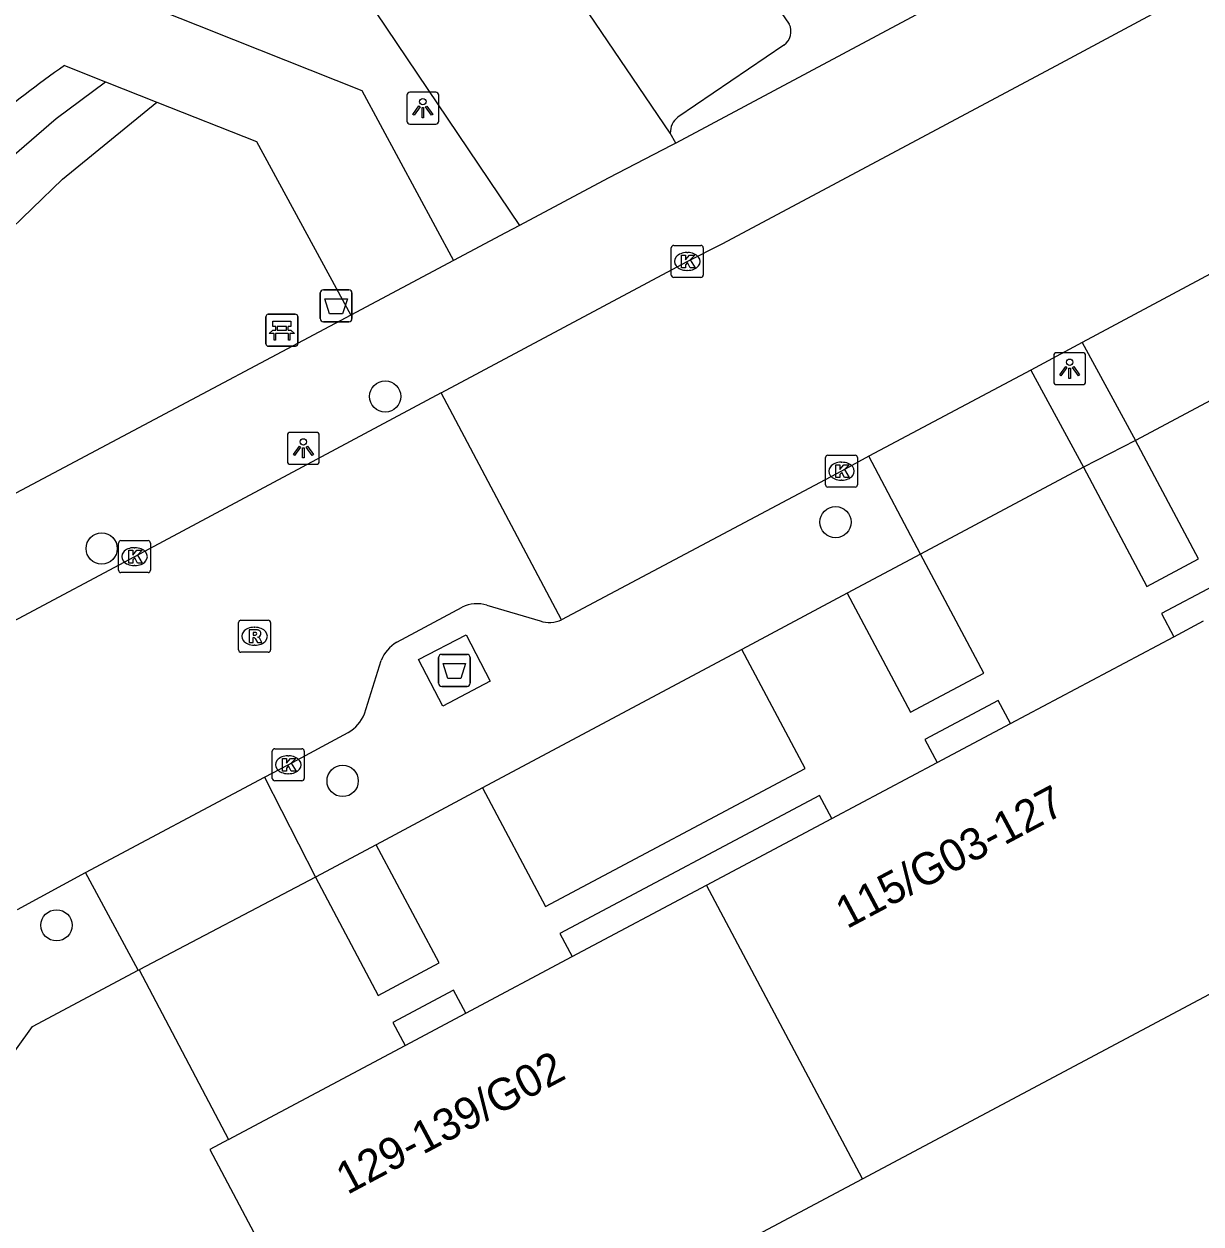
# Model space of a CAD drawing. Extents: x 159675 to 160530, y 382179 to 382901.
# Drawn here: x 159893.75 to 159930.56, y 382360.88 to 382398.41 of the extents above; entities that cross this region are included whole.
import ezdxf

# ---------------------------------------------------------------- set-up
doc = ezdxf.new("R2010")
doc.units = 0
for name, color, linetype in [('IMGEO_Afval_apart_plaats', 7, 'Continuous'), ('IMGEO_Afvalbak', 7, 'Continuous'), ('IMGEO_Bank', 7, 'Continuous'), ('IMGEO_Boom', 7, 'Continuous'), ('IMGEO_Groenvoorziening', 7, 'Continuous'), ('IMGEO_Kolk', 7, 'Continuous'), ('IMGEO_Lichtpunt', 7, 'Continuous'), ('IMGEO_Pand', 7, 'Continuous'), ('IMGEO_Pand_nummerreeks', 7, 'Continuous'), ('IMGEO_Parkeervlak_open', 7, 'Continuous'), ('IMGEO_Rijbaan_lokaal_gesloten', 7, 'Continuous'), ('IMGEO_Rijbaan_lokaal_open', 7, 'Continuous'), ('IMGEO_Rioolput', 7, 'Continuous'), ('IMGEO_Voetpad_gesloten', 7, 'Continuous'), ('IMGEO_Voetpad_open', 7, 'Continuous')]:
    doc.layers.add(name, color=color, linetype=linetype)

msp = doc.modelspace()

# ---------------------------------------------------------------- linework, layer by layer
at = {"layer": 'IMGEO_Afval_apart_plaats'}
for p, q in [((159906.817, 382378.693), (159907.607, 382378.693)), ((159907.607, 382378.693), (159906.817, 382378.693)), ((159906.717, 382377.793), (159906.717, 382378.593)), ((159906.717, 382378.593), (159906.717, 382377.793)), ((159907.707, 382378.593), (159907.707, 382377.793)), ((159907.707, 382377.793), (159907.707, 382378.593)), ((159907.607, 382377.693), (159906.817, 382377.693)), ((159906.817, 382377.693), (159907.607, 382377.693))]:
    msp.add_line(p, q, dxfattribs=at)
msp.add_lwpolyline([(159906.86, 382378.407), (159907.564, 382378.407), (159907.415, 382377.937), (159907.009, 382377.937), (159906.86, 382378.407)], dxfattribs=at)
for centre, start, end in [((159906.817, 382378.593), 90, 180), ((159906.817, 382378.593), 90, 180), ((159907.607, 382378.593), 0, 90), ((159907.607, 382378.593), 360, 90), ((159906.817, 382377.793), 180, 270), ((159906.817, 382377.793), 180, 270), ((159907.607, 382377.793), 270, 0), ((159907.607, 382377.793), 270, 0)]:
    msp.add_arc(centre, 0.1, start, end, dxfattribs=at)
at = {"layer": 'IMGEO_Afvalbak'}
for p, q in [((159903.019, 382389.197), (159903.019, 382389.997)), ((159903.019, 382389.997), (159903.019, 382389.197)), ((159903.119, 382390.097), (159903.909, 382390.097)), ((159903.909, 382390.097), (159903.119, 382390.097)), ((159904.009, 382389.997), (159904.009, 382389.197)), ((159904.009, 382389.197), (159904.009, 382389.997)), ((159903.909, 382389.097), (159903.119, 382389.097)), ((159903.119, 382389.097), (159903.909, 382389.097))]:
    msp.add_line(p, q, dxfattribs=at)
msp.add_lwpolyline([(159903.162, 382389.811), (159903.866, 382389.811), (159903.717, 382389.341), (159903.311, 382389.341), (159903.162, 382389.811)], dxfattribs=at)
for centre, start, end in [((159903.119, 382389.997), 90, 180), ((159903.119, 382389.997), 90, 180), ((159903.909, 382389.997), 0, 90), ((159903.909, 382389.997), 360, 90), ((159903.119, 382389.197), 180, 270), ((159903.119, 382389.197), 180, 270), ((159903.909, 382389.197), 270, 0), ((159903.909, 382389.197), 270, 0)]:
    msp.add_arc(centre, 0.1, start, end, dxfattribs=at)
at = {"layer": 'IMGEO_Bank'}
for p, q in [((159901.318, 382388.408), (159901.318, 382389.249)), ((159901.318, 382389.249), (159901.318, 382388.408)), ((159901.393, 382389.333), (159902.234, 382389.333)), ((159902.234, 382389.333), (159901.393, 382389.333)), ((159902.318, 382389.258), (159902.318, 382388.417)), ((159902.318, 382388.417), (159902.318, 382389.258)), ((159901.627, 382388.839), (159901.627, 382388.945)), ((159901.671, 382388.945), (159901.671, 382388.839)), ((159901.959, 382388.951), (159901.677, 382388.951)), ((159901.677, 382388.833), (159901.959, 382388.833)), ((159901.965, 382388.839), (159901.965, 382388.945)), ((159902.009, 382388.945), (159902.009, 382388.839)), ((159902.015, 382388.731), (159901.622, 382388.731)), ((159902.243, 382388.333), (159901.402, 382388.333)), ((159901.402, 382388.333), (159902.243, 382388.333))]:
    msp.add_line(p, q, dxfattribs=at)
for points in [[(159901.565, 382388.731), (159901.423, 382388.731), (159901.535, 382388.833), (159901.621, 382388.833)], [(159901.621, 382388.951), (159901.535, 382388.951), (159901.535, 382389.112), (159902.098, 382389.112), (159902.098, 382388.951), (159902.015, 382388.951)], [(159902.015, 382388.833), (159902.098, 382388.833), (159902.21, 382388.731), (159902.071, 382388.731)], [(159901.615, 382388.724), (159901.615, 382388.517), (159901.572, 382388.517), (159901.572, 382388.724)], [(159902.065, 382388.724), (159902.065, 382388.517), (159902.021, 382388.517), (159902.021, 382388.724)]]:
    msp.add_lwpolyline(points, dxfattribs=at)
for centre, radius, start, end in [((159901.396, 382389.255), 0.0779, 92.4484, 184.2845), ((159901.396, 382389.255), 0.0779, 92.4484, 184.2845), ((159902.24, 382389.255), 0.0779, 2.4484, 94.2845), ((159902.24, 382389.255), 0.0779, 2.4484, 94.2845), ((159901.62, 382388.944), 0.00671, 2.8957, 87.1043), ((159901.62, 382388.84), 0.00671, 272.8957, 357.1043), ((159901.677, 382388.944), 0.00671, 92.8957, 177.1043), ((159901.677, 382388.84), 0.00671, 182.8957, 267.1043), ((159901.959, 382388.944), 0.00671, 2.8957, 87.1043), ((159901.959, 382388.84), 0.00671, 272.8957, 357.1043), ((159902.016, 382388.944), 0.00671, 92.8957, 177.1043), ((159902.016, 382388.84), 0.00671, 182.8957, 267.1043), ((159901.565, 382388.724), 0.00671, 2.8957, 87.1043), ((159901.622, 382388.724), 0.00671, 92.8957, 177.1043), ((159902.014, 382388.724), 0.00671, 2.8957, 87.1043), ((159902.071, 382388.724), 0.00671, 92.8957, 177.1043), ((159901.396, 382388.411), 0.0779, 182.4484, 274.2845), ((159901.396, 382388.411), 0.0779, 182.4484, 274.2845), ((159902.24, 382388.411), 0.0779, 272.4484, 4.2845), ((159902.24, 382388.411), 0.0779, 272.4484, 4.2845)]:
    msp.add_arc(centre, radius, start, end, dxfattribs=at)
at = {"layer": 'IMGEO_Boom'}
for centre in [(159905.05, 382386.76), (159919.13, 382382.831), (159896.182, 382382.003), (159903.718, 382374.735), (159894.772, 382370.219)]:
    msp.add_circle(centre, 0.489, dxfattribs=at)
at = {"layer": 'IMGEO_Groenvoorziening'}
for points in [[(159880.868, 382381.168), (159884.215, 382385.459), (159885.111, 382386.512), (159888.277, 382389.857), (159894.758, 382395.456), (159896.302, 382396.602)], [(159882.23, 382378.883), (159884.721, 382382.187), (159885.15, 382382.548), (159889.821, 382388.351), (159891.149, 382389.882), (159894.953, 382393.558), (159897.904, 382395.97)]]:
    msp.add_lwpolyline(points, dxfattribs=at)
at = {"layer": 'IMGEO_Kolk'}
for p, q in [((159914.069, 382391.483), (159914.921, 382391.483)), ((159913.994, 382390.557), (159913.994, 382391.409)), ((159914.482, 382391.263), (159914.507, 382391.263)), ((159914.995, 382391.409), (159914.995, 382390.557)), ((159914.505, 382390.703), (159914.48, 382390.703)), ((159914.921, 382390.483), (159914.069, 382390.483)), ((159918.816, 382383.997), (159918.816, 382384.849)), ((159918.891, 382384.923), (159919.743, 382384.923)), ((159919.304, 382384.703), (159919.329, 382384.703)), ((159919.817, 382384.849), (159919.817, 382383.997)), ((159919.327, 382384.143), (159919.302, 382384.143)), ((159919.743, 382383.923), (159918.891, 382383.923)), ((159896.709, 382381.325), (159896.709, 382382.177)), ((159896.784, 382382.251), (159897.636, 382382.251)), ((159897.71, 382382.177), (159897.71, 382381.325)), ((159897.197, 382382.031), (159897.222, 382382.031)), ((159897.22, 382381.471), (159897.195, 382381.471)), ((159897.636, 382381.251), (159896.784, 382381.251)), ((159901.593, 382375.741), (159902.445, 382375.741)), ((159901.518, 382374.815), (159901.518, 382375.667)), ((159902.006, 382375.521), (159902.031, 382375.521)), ((159902.519, 382375.667), (159902.519, 382374.815)), ((159902.029, 382374.961), (159902.004, 382374.961)), ((159902.445, 382374.741), (159901.593, 382374.741))]:
    msp.add_line(p, q, dxfattribs=at)
for points in [[(159914.069, 382391.483), (159914.921, 382391.483)], [(159913.994, 382390.557), (159913.994, 382391.409)], [(159914.315, 382391.183), (159914.438, 382391.183), (159914.438, 382391.032), (159914.568, 382391.183), (159914.732, 382391.183), (159914.586, 382391.032), (159914.739, 382390.783), (159914.587, 382390.783), (159914.502, 382390.947), (159914.438, 382390.88), (159914.438, 382390.783), (159914.315, 382390.783), (159914.315, 382391.183)], [(159914.995, 382391.409), (159914.995, 382390.557)], [(159914.921, 382390.483), (159914.069, 382390.483)], [(159918.816, 382383.997), (159918.816, 382384.849)], [(159918.891, 382384.923), (159919.743, 382384.923)], [(159919.817, 382384.849), (159919.817, 382383.997)], [(159919.137, 382384.623), (159919.26, 382384.623), (159919.26, 382384.472), (159919.39, 382384.623), (159919.554, 382384.623), (159919.408, 382384.472), (159919.561, 382384.223), (159919.409, 382384.223), (159919.324, 382384.387), (159919.26, 382384.32), (159919.26, 382384.223), (159919.137, 382384.223), (159919.137, 382384.623)], [(159919.743, 382383.923), (159918.891, 382383.923)], [(159896.709, 382381.325), (159896.709, 382382.177)], [(159896.784, 382382.251), (159897.636, 382382.251)], [(159897.71, 382382.177), (159897.71, 382381.325)], [(159897.03, 382381.951), (159897.153, 382381.951), (159897.153, 382381.8), (159897.283, 382381.951), (159897.447, 382381.951), (159897.301, 382381.8), (159897.454, 382381.551), (159897.302, 382381.551), (159897.217, 382381.715), (159897.153, 382381.648), (159897.153, 382381.551), (159897.03, 382381.551), (159897.03, 382381.951)], [(159897.636, 382381.251), (159896.784, 382381.251)], [(159901.593, 382375.741), (159902.445, 382375.741)], [(159901.518, 382374.815), (159901.518, 382375.667)], [(159901.839, 382375.441), (159901.962, 382375.441), (159901.962, 382375.29), (159902.092, 382375.441), (159902.256, 382375.441), (159902.11, 382375.29), (159902.263, 382375.041), (159902.111, 382375.041), (159902.026, 382375.205), (159901.962, 382375.138), (159901.962, 382375.041), (159901.839, 382375.041), (159901.839, 382375.441)], [(159902.519, 382375.667), (159902.519, 382374.815)], [(159902.445, 382374.741), (159901.593, 382374.741)]]:
    msp.add_lwpolyline(points, dxfattribs=at)
for centre, start, end in [((159914.071, 382391.407), 91.552, 178.448), ((159914.071, 382391.407), 91.552, 178.448), ((159914.919, 382391.407), 1.552, 88.448), ((159914.919, 382391.407), 1.552, 88.448), ((159914.071, 382390.559), 181.552, 268.448), ((159914.071, 382390.559), 181.552, 268.448), ((159914.919, 382390.559), 271.552, 358.448), ((159914.919, 382390.559), 271.552, 358.448), ((159918.893, 382384.847), 91.552, 178.448), ((159918.893, 382384.847), 91.552, 178.448), ((159919.741, 382384.847), 1.552, 88.448), ((159919.741, 382384.847), 1.552, 88.448), ((159918.893, 382383.999), 181.552, 268.448), ((159918.893, 382383.999), 181.552, 268.448), ((159919.741, 382383.999), 271.552, 358.448), ((159919.741, 382383.999), 271.552, 358.448), ((159896.786, 382382.175), 91.552, 178.448), ((159896.786, 382382.175), 91.552, 178.448), ((159897.634, 382382.175), 1.552, 88.448), ((159897.634, 382382.175), 1.552, 88.448), ((159896.786, 382381.327), 181.552, 268.448), ((159896.786, 382381.327), 181.552, 268.448), ((159897.634, 382381.327), 271.552, 358.448), ((159897.634, 382381.327), 271.552, 358.448), ((159901.595, 382375.665), 91.552, 178.448), ((159901.595, 382375.665), 91.552, 178.448), ((159902.443, 382375.665), 1.552, 88.448), ((159902.443, 382375.665), 1.552, 88.448), ((159901.595, 382374.817), 181.552, 268.448), ((159901.595, 382374.817), 181.552, 268.448), ((159902.443, 382374.817), 271.552, 358.448), ((159902.443, 382374.817), 271.552, 358.448)]:
    msp.add_arc(centre, 0.0765, start, end, dxfattribs=at)
for centre, major_axis, ratio, start_param, end_param in [((159914.481, 382390.983), (-0.387, 0.002), 0.722429, 4.712389, 7.853982), ((159914.506, 382390.983), (-0.39, 0.002), 0.717154, 1.570796, 4.712389), ((159919.303, 382384.423), (-0.387, 0.002), 0.722429, 4.712389, 7.853982), ((159919.328, 382384.423), (-0.39, 0.002), 0.717154, 1.570796, 4.712389), ((159897.196, 382381.751), (-0.387, 0.002), 0.722429, 4.712389, 7.853982), ((159897.221, 382381.751), (-0.39, 0.002), 0.717154, 1.570796, 4.712389), ((159902.005, 382375.241), (-0.387, 0.002), 0.722429, 4.712389, 7.853982), ((159902.03, 382375.241), (-0.39, 0.002), 0.717154, 1.570796, 4.712389)]:
    msp.add_ellipse(centre, major_axis=major_axis, ratio=ratio, start_param=start_param, end_param=end_param, dxfattribs=at)
at = {"layer": 'IMGEO_Lichtpunt'}
for p, q in [((159905.726, 382396.182), (159905.726, 382395.375)), ((159905.726, 382396.182), (159905.726, 382395.375)), ((159906.628, 382396.277), (159905.82, 382396.277)), ((159906.628, 382396.277), (159905.82, 382396.277)), ((159906.722, 382395.375), (159906.722, 382396.182)), ((159906.722, 382395.375), (159906.722, 382396.182)), ((159905.82, 382395.281), (159906.628, 382395.281)), ((159905.82, 382395.281), (159906.628, 382395.281)), ((159926.855, 382388.128), (159926.047, 382388.128)), ((159926.855, 382388.128), (159926.047, 382388.128)), ((159925.953, 382388.033), (159925.953, 382387.226)), ((159925.953, 382388.033), (159925.953, 382387.226)), ((159926.949, 382387.226), (159926.949, 382388.033)), ((159926.949, 382387.226), (159926.949, 382388.033)), ((159926.047, 382387.132), (159926.855, 382387.132)), ((159926.047, 382387.132), (159926.855, 382387.132)), ((159901.991, 382385.542), (159901.991, 382384.735)), ((159901.991, 382385.542), (159901.991, 382384.735)), ((159902.893, 382385.637), (159902.085, 382385.637)), ((159902.893, 382385.637), (159902.085, 382385.637)), ((159902.987, 382384.735), (159902.987, 382385.542)), ((159902.987, 382384.735), (159902.987, 382385.542)), ((159902.085, 382384.641), (159902.893, 382384.641)), ((159902.085, 382384.641), (159902.893, 382384.641))]:
    msp.add_line(p, q, dxfattribs=at)
for points in [[(159906.1, 382395.846), (159906.139, 382395.818), (159905.951, 382395.556), (159905.913, 382395.583), (159906.1, 382395.846)], [(159906.202, 382395.798), (159906.249, 382395.798), (159906.249, 382395.476), (159906.202, 382395.476), (159906.202, 382395.798)], [(159906.312, 382395.818), (159906.35, 382395.845), (159906.537, 382395.583), (159906.498, 382395.555), (159906.312, 382395.818)], [(159926.327, 382387.697), (159926.366, 382387.669), (159926.178, 382387.407), (159926.14, 382387.434), (159926.327, 382387.697)], [(159926.429, 382387.649), (159926.476, 382387.649), (159926.476, 382387.327), (159926.429, 382387.327), (159926.429, 382387.649)], [(159926.539, 382387.669), (159926.577, 382387.696), (159926.764, 382387.434), (159926.725, 382387.406), (159926.539, 382387.669)], [(159902.365, 382385.206), (159902.404, 382385.178), (159902.216, 382384.916), (159902.178, 382384.943), (159902.365, 382385.206)], [(159902.467, 382385.158), (159902.514, 382385.158), (159902.514, 382384.836), (159902.467, 382384.836), (159902.467, 382385.158)], [(159902.577, 382385.178), (159902.615, 382385.205), (159902.802, 382384.943), (159902.763, 382384.915), (159902.577, 382385.178)]]:
    msp.add_lwpolyline(points, dxfattribs=at)
for centre in [(159906.225, 382395.98), (159926.452, 382387.831), (159902.49, 382385.34)]:
    msp.add_circle(centre, 0.0994, dxfattribs=at)
for centre, start, end in [((159905.82, 382396.182), 90, 180), ((159905.82, 382396.182), 90, 180), ((159906.628, 382396.182), 0, 90), ((159906.628, 382396.182), 0, 90), ((159905.82, 382395.375), 180, 270), ((159905.82, 382395.375), 180, 270), ((159906.628, 382395.375), 270, 0), ((159906.628, 382395.375), 270, 360), ((159926.047, 382388.033), 90, 180), ((159926.047, 382388.033), 90, 180), ((159926.855, 382388.033), 0, 90), ((159926.855, 382388.033), 0, 90), ((159926.047, 382387.226), 180, 270), ((159926.047, 382387.226), 180, 270), ((159926.855, 382387.226), 270, 0), ((159926.855, 382387.226), 270, 360), ((159902.085, 382385.542), 90, 180), ((159902.085, 382385.542), 90, 180), ((159902.893, 382385.542), 0, 90), ((159902.893, 382385.542), 0, 90), ((159902.085, 382384.735), 180, 270), ((159902.085, 382384.735), 180, 270), ((159902.893, 382384.735), 270, 0), ((159902.893, 382384.735), 270, 360)]:
    msp.add_arc(centre, 0.0946, start, end, dxfattribs=at)
at = {"layer": 'IMGEO_Pand'}
for points in [[(159929.706, 382379.247), (159930.634, 382379.741)], [(159924.602, 382376.531), (159929.706, 382379.247)], [(159922.312, 382375.313), (159924.602, 382376.531)], [(159919.013, 382373.558), (159922.312, 382375.313)], [(159915.097, 382371.474), (159919.013, 382373.558)], [(159910.898, 382369.24), (159915.097, 382371.474)], [(159919.971, 382362.292), (159915.097, 382371.474)], [(159919.971, 382362.292), (159935.509, 382370.559)], [(159907.573, 382367.47), (159910.898, 382369.24)], [(159905.67, 382366.457), (159907.573, 382367.47)], [(159900.148, 382363.519), (159905.67, 382366.457)], [(159900.148, 382363.519), (159899.56, 382363.206), (159904.434, 382354.024), (159919.971, 382362.292)]]:
    msp.add_lwpolyline(points, dxfattribs=at)
at = {"layer": 'IMGEO_Parkeervlak_open'}
for points in [[(159910.599, 382408.715), (159917.683, 382398.41)], [(159917.518, 382397.744), (159914.199, 382395.496)]]:
    msp.add_lwpolyline(points, dxfattribs=at)
for centre, radius, start, end in [((159917.207, 382398.174), 0.531, 305.8437, 26.3268), ((159914.584, 382395.008), 0.621, 128.3122, 181.3295)]:
    msp.add_arc(centre, radius, start, end, dxfattribs=at)
at = {"layer": 'IMGEO_Rijbaan_lokaal_gesloten'}
for points in [[(159906.798, 382386.87), (159914.495, 382390.981), (159915.606, 382391.545), (159926.173, 382397.188), (159931.751, 382400.186), (159948.098, 382408.904), (159951.117, 382410.379), (159963.588, 382417.082)], [(159932.202, 382391.318), (159926.838, 382388.444)], [(159926.838, 382388.444), (159925.235, 382387.585)], [(159925.235, 382387.585), (159920.172, 382384.892)], [(159910.565, 382379.779), (159906.798, 382386.87)], [(159920.172, 382384.892), (159919.315, 382384.424), (159910.565, 382379.779)]]:
    msp.add_lwpolyline(points, dxfattribs=at)
at = {"layer": 'IMGEO_Rijbaan_lokaal_open'}
for points in [[(159868.258, 382453.114), (159889.372, 382421.597), (159909.248, 382392.109)], [(159913.963, 382394.994), (159905.969, 382406.788)], [(159914.132, 382394.686), (159913.963, 382394.994)], [(159914.132, 382394.686), (159914.011, 382394.622), (159912.019, 382393.591), (159909.248, 382392.109)], [(159906.798, 382386.87), (159897.21, 382381.749), (159889.919, 382377.867)], [(159908.231, 382380.233), (159909.892, 382379.74)], [(159905.415, 382379.071), (159907.452, 382380.17)], [(159904.397, 382376.829), (159904.922, 382378.503)], [(159901.269, 382374.853), (159902.019, 382375.242), (159903.894, 382376.255)], [(159895.682, 382371.875), (159901.269, 382374.853)], [(159893.546, 382370.71), (159895.682, 382371.875)]]:
    msp.add_lwpolyline(points, dxfattribs=at)
for centre, radius, start, end in [((159907.923, 382379.191), 1.086, 73.5436, 115.7036), ((159910.183, 382380.552), 0.863, 250.3129, 296.3202), ((159905.996, 382378.069), 1.158, 120.0976, 157.9892), ((159903.361, 382377.229), 1.11, 298.6694, 338.874)]:
    msp.add_arc(centre, radius, start, end, dxfattribs=at)
at = {"layer": 'IMGEO_Rioolput'}
for p, q in [((159900.462, 382378.834), (159900.462, 382379.686)), ((159900.537, 382379.76), (159901.389, 382379.76)), ((159900.95, 382379.54), (159900.975, 382379.54)), ((159901.463, 382379.686), (159901.463, 382378.834)), ((159901.389, 382378.76), (159900.537, 382378.76)), ((159900.973, 382378.98), (159900.948, 382378.98))]:
    msp.add_line(p, q, dxfattribs=at)
for points in [[(159900.462, 382378.834), (159900.462, 382379.686)], [(159900.537, 382379.76), (159901.389, 382379.76)], [(159901.051, 382379.458), (159900.799, 382379.46), (159900.799, 382379.06)], [(159901.463, 382379.686), (159901.463, 382378.834)], [(159900.799, 382379.06), (159900.923, 382379.06), (159900.923, 382379.222), (159900.934, 382379.222)], [(159900.977, 382379.379), (159900.923, 382379.379), (159900.923, 382379.298)], [(159900.923, 382379.298), (159900.975, 382379.298)], [(159900.981, 382379.193), (159901.052, 382379.06), (159901.192, 382379.06), (159901.127, 382379.186)], [(159901.389, 382378.76), (159900.537, 382378.76)]]:
    msp.add_lwpolyline(points, dxfattribs=at)
for centre, radius, start, end in [((159900.539, 382379.684), 0.0765, 91.552, 178.448), ((159900.539, 382379.684), 0.0765, 91.552, 178.448), ((159901.05, 382379.348), 0.109, 350.3612, 89.416), ((159901.387, 382379.684), 0.0765, 1.552, 88.448), ((159901.387, 382379.684), 0.0765, 1.552, 88.448), ((159900.933, 382379.169), 0.0533, 26.0293, 88.6989), ((159900.959, 382379.487), 0.19, 274.7715, 282.9687), ((159900.983, 382379.283), 0.0964, 77.0061, 93.1865), ((159900.997, 382379.34), 0.0378, 276.6634, 79.6772), ((159901.048, 382379.348), 0.112, 277.5842, 350.9817), ((159901.032, 382379.133), 0.108, 29.5134, 73.7905), ((159900.539, 382378.836), 0.0765, 181.552, 268.448), ((159900.539, 382378.836), 0.0765, 181.552, 268.448), ((159901.387, 382378.836), 0.0765, 271.552, 358.448), ((159901.387, 382378.836), 0.0765, 271.552, 358.448)]:
    msp.add_arc(centre, radius, start, end, dxfattribs=at)
for centre, major_axis, ratio, start_param, end_param in [((159900.949, 382379.26), (-0.387, 0.002), 0.722429, 4.712389, 7.853982), ((159900.974, 382379.26), (-0.39, 0.002), 0.717154, 1.570796, 4.712389)]:
    msp.add_ellipse(centre, major_axis=major_axis, ratio=ratio, start_param=start_param, end_param=end_param, dxfattribs=at)
at = {"layer": 'IMGEO_Voetpad_gesloten'}
msp.add_lwpolyline([(159906.088, 382378.532), (159907.576, 382379.309), (159908.336, 382377.854), (159906.848, 382377.077), (159906.088, 382378.532)], dxfattribs=at)
at = {"layer": 'IMGEO_Voetpad_open'}
for points in [[(159927.732, 382401.96), (159924.556, 382400.256), (159914.132, 382394.686)], [(159891.451, 382399.544), (159893.207, 382400.75), (159899.174, 382398.377), (159900.301, 382397.928), (159904.315, 382396.332), (159907.181, 382391.009)], [(159895.015, 382397.11), (159896.302, 382396.602)], [(159896.302, 382396.602), (159897.904, 382395.97)], [(159897.904, 382395.97), (159901.026, 382394.738), (159903.975, 382389.305)], [(159909.248, 382392.109), (159908.813, 382391.876), (159907.181, 382391.009)], [(159907.181, 382391.009), (159903.975, 382389.305)], [(159903.975, 382389.305), (159889.684, 382381.711)], [(159926.838, 382388.444), (159928.509, 382385.387)], [(159933.872, 382388.24), (159928.509, 382385.387)], [(159925.235, 382387.585), (159926.887, 382384.546)], [(159928.509, 382385.387), (159926.887, 382384.546)], [(159926.887, 382384.546), (159928.87, 382380.819), (159930.483, 382381.677), (159928.509, 382385.387)], [(159921.783, 382381.829), (159920.172, 382384.892)], [(159926.887, 382384.546), (159921.783, 382381.829)], [(159921.783, 382381.829), (159919.496, 382380.607)], [(159919.496, 382380.607), (159921.476, 382376.885), (159923.766, 382378.103), (159921.783, 382381.829)], [(159919.496, 382380.607), (159916.2, 382378.847)], [(159931.319, 382380.106), (159930.935, 382380.828), (159929.322, 382379.97), (159929.706, 382379.247)], [(159916.2, 382378.847), (159908.091, 382374.515)], [(159908.091, 382374.515), (159910.062, 382370.811), (159918.177, 382375.129), (159916.2, 382378.847)], [(159924.602, 382376.531), (159924.218, 382377.253), (159921.928, 382376.035), (159922.312, 382375.313)], [(159901.269, 382374.853), (159902.867, 382371.724)], [(159908.091, 382374.515), (159904.769, 382372.74)], [(159919.013, 382373.558), (159918.629, 382374.28), (159910.514, 382369.961), (159910.898, 382369.24)], [(159904.769, 382372.74), (159902.867, 382371.724)], [(159902.867, 382371.724), (159904.833, 382368.029), (159906.737, 382369.042), (159904.769, 382372.74)], [(159897.322, 382368.812), (159895.682, 382371.875)], [(159902.867, 382371.724), (159897.359, 382368.831)], [(159925.951, 382331.335), (159899.107, 382350.689), (159896.041, 382352.9), (159893.426, 382354.811), (159888.032, 382358.712), (159894.018, 382367.057), (159897.322, 382368.812)], [(159897.322, 382368.812), (159897.359, 382368.831)], [(159897.359, 382368.831), (159900.148, 382363.519)], [(159907.573, 382367.47), (159907.189, 382368.192), (159905.286, 382367.179), (159905.67, 382366.457)]]:
    msp.add_lwpolyline(points, dxfattribs=at)
msp.add_arc((159915.978, 382367.257), 36.478, 125.0759, 134.6581, dxfattribs=at)

# ---------------------------------------------------------------- texts
at = {"layer": 'IMGEO_Pand_nummerreeks'}
for s, p in [('115/G03-127', (159919.485, 382370.093)), ('129-139/G02', (159903.864, 382361.781))]:
    msp.add_text(s, height=1, rotation=28.0176, dxfattribs=at).set_placement(p)

doc.saveas('drawing.dxf')
